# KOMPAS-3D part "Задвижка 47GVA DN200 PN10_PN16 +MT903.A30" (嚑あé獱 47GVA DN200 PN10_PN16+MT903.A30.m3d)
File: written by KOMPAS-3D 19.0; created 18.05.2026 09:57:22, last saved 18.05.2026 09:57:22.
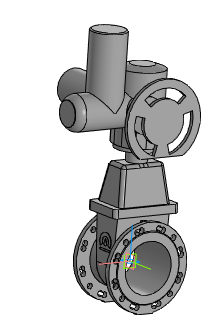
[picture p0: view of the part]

Document properties: Автор: Энергия; Полное имя файла: ..\Задвижка 47GVA DN50_DN1000+MT903.A\Задвижка 47GVA DN200 PN10_PN16+MT903.A30.a3d

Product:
- Part/product: Задвижка 47GVA DN200 PN10_PN16 +MT903.A30
    Масса: 260.514
  - Body: Электропривод МТ903.А30 без блока управления
      Масса: 163.268
  - Body: Задвижка 47GVA DN200 PN10_PN16 без исполнит. мех.
      Масса: 97.2454

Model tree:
1. Операция без истории:1
2. Операция без истории:2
